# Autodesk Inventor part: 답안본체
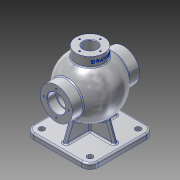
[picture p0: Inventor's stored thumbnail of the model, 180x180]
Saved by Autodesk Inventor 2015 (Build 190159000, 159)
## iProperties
Created: 2025-08
Part Number: 답안본체
Material: 알루미늄 6061
Document SubType Name: Modeling
Designer: user
Density: 2.7 g/cm^3
Appearance: 알루미늄 - 평지
Mass: 1526.68 g
Surface Area: 1174.39 cm^2
Volume: 565.437 cm^3
Author: user
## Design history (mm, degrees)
sketch "스케치2"
  geometry: L1 (-62.5, -62.5)-(62.5, -62.5); L2 (62.5, -62.5)-(62.5, 62.5); L3 (62.5, 62.5)-(-62.5, 62.5); L4 (-62.5, 62.5)-(-62.5, -62.5); L5 (-62.5, -62.5)-(62.5, 62.5); L6 (62.5, -62.5)-(-62.5, 62.5); 1 further point
  constraints: 12 end point, 2 midpoint, 2 parallel, 1 horizontal, 1 perpendicular
  dimensions: "d0" = 125 distance of L3.end L2.end; "d1" = 125 distance of L2.end L1.end
extrude "돌출1" new body sketch "스케치2" distance "d2" = 10; taper "d3" = 0 deg
sketch "스케치6"
  geometry: L1 (-62.5, 0)-(-62.5, 10) reference; L2 (-62.5, 10)-(62.5, 10) reference; L3 (62.5, 10)-(62.5, 0) reference; L4 (62.5, 0)-(-62.5, 0) reference; L5 (0, 139)-(0, 31); A1 r 54 centre (0, 85) between (0, 139) and (0, 31); 3 further points
  constraints: 2 end point, 2 midpoint, 2 point on circle, 2 vertical alignment, 1 centre point, 1 coincident, 1 vertical
  dimensions: "d11" = 108 diameter of A1; "d12" = 85 distance from line of A1.centre L4
revolve "회전3" sketch "스케치6" stored, may be unused: angle "d13" = 90 deg
node "작업 평면1"
sketch "스케치7"
  geometry: C1 r 27 at (0, 0); 1 further point
  constraints: 1 centre point, 1 coincident
  dimensions: "d15" = 54 diameter of C1
extrude "돌출2" join sketch "스케치7" stored distance "d16" = 10; taper "d17" = 0 deg
sketch "스케치9"
  geometry: L1 (62.5, -62.5)-(-62.5, -62.5) reference; L2 (-62.5, -62.5)-(-62.5, 62.5) reference; L3 (-62.5, 62.5)-(62.5, 62.5) reference; L4 (62.5, 62.5)-(62.5, -62.5) reference; L5 (-4, -50.5)-(4, -50.5); L6 (4, -50.5)-(4, 50.5); L7 (4, 50.5)-(-4, 50.5); L8 (-4, 50.5)-(-4, -50.5); L9 (-4, -50.5)-(4, 50.5); L10 (4, -50.5)-(-4, 50.5); L11 (-50.5, -4)-(50.5, -4); L12 (50.5, -4)-(50.5, 4); L13 (50.5, 4)-(-50.5, 4); L14 (-50.5, 4)-(-50.5, -4); L15 (-50.5, -4)-(50.5, 4); L16 (50.5, -4)-(-50.5, 4); 1 further point
  constraints: 24 end point, 4 midpoint, 4 parallel, 2 horizontal, 2 perpendicular
  dimensions: "d26" = 8 distance of L6.end L7.end; "d27" = 8 distance of L11.end L12.end; "d28" = 12 distance between parallel lines of L12 L4; "d29" = 12 distance between parallel lines of L7 L3
extrude "돌출4" join sketch "스케치9" distance "d30" = 90; taper "d31" = 0 deg
feature "면 기울기1" dims angle "d32" = 20 deg
node "작업 평면2"
sketch "스케치10"
  geometry: L1 (62.5, 0)-(-62.5, 0) reference; C1 r 31 at (0, 85); 2 further points
  constraints: 1 centre point, 1 midpoint, 1 vertical alignment
  dimensions: "d34" = 62 diameter of C1; "d35" = 85 distance from line of C1.centre L1
extrude "돌출5" join sketch "스케치10" distance "d36" = 130; taper "d37" = 0 deg
sketch "스케치11"
  geometry: L1 (-27, 131.765)-(-27, 150) reference; L2 (-27, 150)-(27, 150) reference; L3 (27, 150)-(27, 131.765) reference; L4 (37.385, 46.034)-(50.5, 10) reference; L5 (50.5, 10)-(62.5, 10) reference; L6 (62.5, 10)-(62.5, 0) reference; L7 (62.5, 0)-(-62.5, 0) reference; L8 (-62.5, 0)-(-62.5, 10) reference; L9 (-62.5, 10)-(-50.5, 10) reference; L10 (-50.5, 10)-(-37.385, 46.034) reference; L11 (0, 129)-(0, 41); A1 r 54 centre (0, 85) between (37.385, 46.034) and (27, 131.765) reference; A2 r 54 centre (0, 85) between (-27, 131.765) and (-37.385, 46.034) reference; A3 r 44 centre (0, 85) between (0, 129) and (0, 41); 3 further points
  constraints: 2 coincident, 2 end point, 2 midpoint, 2 point on circle, 1 centre point, 1 vertical, 1 vertical alignment
  dimensions: "d38" = 88 diameter of A3
revolve "회전4" sketch "스케치11" stored, may be unused: angle "d39" = 90 deg
sketch "스케치14"
  geometry: C1 r 27 at (0, 0) reference; C2 r 13 at (0, 0); 1 further point
  constraints: 1 centre point, 1 coincident
  dimensions: "d41" = 26 diameter of C2
extrude "돌출6" cut sketch "스케치14" distance "d42" = 40; taper "d43" = 0 deg
hole "구멍1" diameter "d46" = 30; stored, may be unused: countersink angle "d50" = 90 deg, drill point angle "d52" = 0 deg; dims "d44" = 10, "d45" = 10, "d47" = 12, "d48" = 35, "d49" = 16, "d51" = 30
sketch "스케치19"
  geometry: L1 (0, 0)-(0, 24); C1 r 17.5 at (0, 0) reference; 1 further point
  constraints: 2 end point, 1 vertical
  dimensions: "d54" = 24 distance of L1.start L1.end
hole "구멍2" sketch "스케치19" at (0, 24) diameter "d55" = 3.242; stored, may be unused: countersink angle "d59" = 90 deg, drill point angle "d61" = 118 deg; dims "d56" = 12, "d57" = 35, "d58" = 16, "d60" = 15
sketch "스케치20"
  geometry: L1 (0, 0)-(0, 20)
  constraints: 2 end point, 1 vertical
  dimensions: "d65" = 20 distance of L1.start L1.end
hole "구멍3" sketch "스케치20" at (0, 20) diameter "d66" = 3.242; stored, may be unused: countersink angle "d70" = 90 deg, drill point angle "d72" = 118 deg; dims "d67" = 9, "d68" = 35, "d69" = 16, "d71" = 11
node "작업 평면3"
sketch "스케치21"
  geometry: L1 (-27, 150)-(27, 150) reference; 2 further points
  constraints: 1 vertical alignment, 1 other
  dimensions: "d77" = 9 distance from line of point (0, 141) L1
feature "엠보싱1" sketch "스케치21" dims "d0" = 125, "d1" = 125, "d78" = 0.5, "d79" = 0
fillet "모깎기1" dims "d80" = 3
fillet "모깎기2" dims "d81" = 3
fillet "모깎기3" dims "d82" = 3
fillet "모깎기4" dims "d83" = 16
hole "구멍4" diameter "d86" = 11; stored, may be unused: countersink angle "d90" = 90 deg, drill point angle "d92" = 118 deg; dims "d84" = 10, "d85" = 10, "d87" = 9, "d88" = 35, "d89" = 16, "d91" = 11
hole "구멍5" diameter "d95" = 11; stored, may be unused: countersink angle "d99" = 90 deg, drill point angle "d101" = 118 deg; dims "d93" = 10, "d94" = 10, "d96" = 9, "d97" = 35, "d98" = 16, "d100" = 11
hole "구멍6" diameter "d104" = 11; stored, may be unused: countersink angle "d108" = 90 deg, drill point angle "d110" = 118 deg; dims "d102" = 10, "d103" = 10, "d105" = 9, "d106" = 35, "d107" = 16, "d109" = 11
hole "구멍7" diameter "d113" = 11; stored, may be unused: countersink angle "d117" = 90 deg, drill point angle "d119" = 118 deg; dims "d111" = 10, "d112" = 10, "d114" = 9, "d115" = 35, "d116" = 16, "d118" = 11
fillet "모깎기5" dims "d120" = 3
chamfer "모따기1" distance "d121" = 1; stored, may be unused: second distance "d122" = 2, angle "d123" = 45 deg
node "솔리드1"
mirror "대칭1"
pattern_circular "원형 패턴1" dims angle "d63" = 360 deg
mirror "대칭2"
pattern_circular "원형 패턴2" dims angle "d74" = 360 deg
node "절단 모서리 투영1"
node "절단 모서리 투영3"
node "절단 모서리 투영4"
node "절단 모서리 투영5"
other parameters: "d33" = -65, "d76" = 142.5
